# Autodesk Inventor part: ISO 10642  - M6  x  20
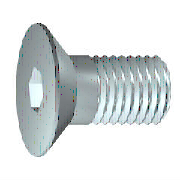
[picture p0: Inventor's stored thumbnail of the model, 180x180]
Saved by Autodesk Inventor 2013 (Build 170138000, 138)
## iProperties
IsCustomPart: 0
Created: 2012-02
Part Number: ISO 10642  - M6  x  20
Material: Stahl
Description: Innensechskantschraube mit Senkkopf
Document SubType Name: Modeling
Standard: ISO 10642
Designer: rYan
Standard Revision: 1998
Standards Organization: DIN
Language: de-DE
Size Designation: M6  x  20
Categories: <MemberInstance><Categories><Category DisplayName="Verbindungselemente" InternalName="e4da775c-781d-43d5-af7c-5136215cf5a6" Mnemonic="FSTN"><Category DisplayNam
Density: 7.85 g/cm^3
Author: rYan
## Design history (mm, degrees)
body "Solid1"
revolve "Körper" stored, may be unused: angle "d13" = 90 deg
sketch "Skizze2"
  geometry: L1 (0, -7.938)-(0, 7.938) reference; L2 (-7.938, 0)-(7.938, 0) reference; L3 (2.309, 0)-(1.155, -2); L4 (1.155, -2)-(-1.155, -2); L5 (-1.155, -2)-(-2.309, 0); L6 (-2.309, 0)-(-1.155, 2); L7 (-1.155, 2)-(1.155, 2); L8 (1.155, 2)-(2.309, 0); A1 r 2.309 centre (0, 0) between (0, 2.309) and (2.309, 0) reference; 2 further points
  constraints: 12 end point, 2 coincident, 2 point on circle, 2 point on line, 12 other
extrude "Loch" join sketch "Skizze2" taper "d14" = 0 deg; stored distance "d30" = 10
feature "Gewinde" dims "d15" = 13.67 (= GEL), "d16" = 0
chamfer "Fase1" distance "d17" = 0.61345 (= -0.5 x SPD + 0.5 x GD); stored, may be unused: second distance "d18" = 0.61345 (= GUL), angle "d39" = 45 deg
workplane "Work Plane1"
sketch "Skizze1"
  geometry: L1 (20, 0)-(20, 3); L2 (20, 3)-(6.33, 3); L3 (6.33, 3)-(5.717, 3); L4 (0, 5.67)-(0, 2.309); L5 (0, 2.309)-(2.2, 2.309); L6 (2.2, 2.309)-(3.533, 0); L7 (3.533, 0)-(20, 0); L8 (0, 5.67)-(1.05, 5.67); L9 (1.05, 5.67)-(3.72, 3); L10 (5.717, 3)-(3.72, 3); L11 (6.33, 3)-(3.72, 3); L12 (3.72, 3)-(3.72, 3); L13 (-4, 0)-(24, 0) reference; L14 (0, -1.134)-(0, 6.804) reference
  constraints: 24 end point, 4 collinear, 3 parallel
  dimensions: "d0" = 20 distance between parallel lines of L4 L1 (= NLG); "d1" = 13.67 distance from line of L2.end L1 (= GEL); "d2" = 2.2 distance from line of L5.end L4 (= INTI); "d3" = 6 diameter of L2 L7 (= GD); "d6" = 3.72 distance from line of L9.end L4 (= KOH); "d7" = 45 deg angle of L9 L7 (= 0.5 x SEWI); "d8" = 4.6188 diameter of L5 L7 (= 1.1547 x SW); "d9" = 60 deg angle of L6 L7; "d10" = 11.34 diameter of L8 L7 (= KOD); "d11" = 6 diameter of L10 L7 (= BDM); "d12" = 0.61345 distance of L3.end L2.end (= GAL)
other parameters: "NLG" = 20 [user parameter; used in 1 equation term], "INTI" = 2.2 [user parameter; used in 1 equation term], "GEL" = 13.67 [user parameter; used in 2 equation terms], "GAL" = 0.61345 (= 0.61345 x PTC) [user parameter; used in 1 equation term], "KOH" = 3.72 [user parameter; used in 1 equation term], "KOD" = 11.34 [user parameter; used in 1 equation term], "GUL" = 0.61345 (= 0.61345 x PTC) [user parameter; used in 1 equation term], "SPD" = 4.7731 (= NND - 1.2269 x PTC) [user parameter; used in 1 equation term], "BDM" = 6 (= NND) [user parameter; used in 1 equation term], "GD" = 6 (= NND) [user parameter; used in 2 equation terms], "SEWI" = 90 deg [user parameter; used in 1 equation term], "d20" = 0, "SW" = 4 [user parameter; used in 1 equation term], "d43" = 0, "d44" = 0, "TOA" = 30 deg [user parameter], "GD1" = 4.7731 (= THREADDIA - 1.2269 x PTC) [user parameter], "EPV" = 6.72 [user parameter], "THREADDIA" = 6 [user parameter; used in 1 equation term], "PTC" = 1 [user parameter; used in 5 equation terms], "NND" = 6 [user parameter; used in 3 equation terms], "E0" = 4.62 [user parameter]
